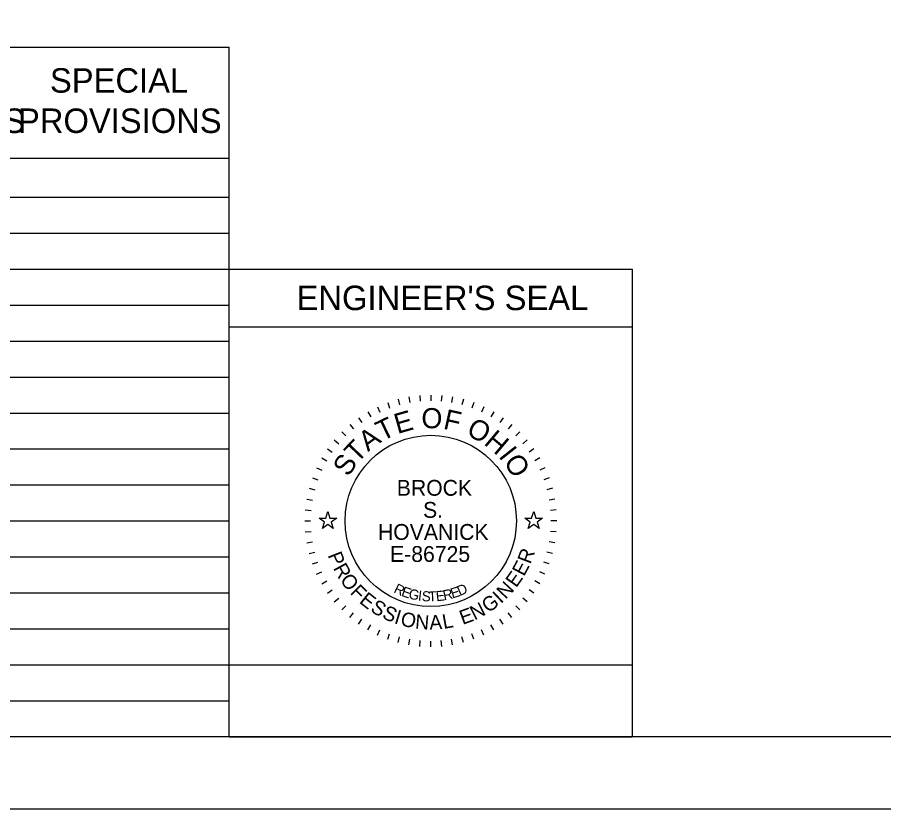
# Model space of a CAD drawing. Extents: x 0 to 34, y 0 to 22.
# Drawn here: x 22.13 to 28.15, y 0 to 5.5 of the extents above; entities that cross this region are included whole.
import ezdxf

# ---------------------------------------------------------------- set-up
doc = ezdxf.new("R2010")
doc.units = 0
for name, color, linetype in [('Default', 7, 'Continuous'), ('SH_Border', 7, 'Continuous'), ('SH_Cut_Line', 7, 'Continuous'), ('SH_Data', 7, 'Continuous'), ('SH_Text', 7, 'Continuous')]:
    doc.layers.add(name, color=color, linetype=linetype)

msp = doc.modelspace()

# ---------------------------------------------------------------- linework, layer by layer
at = {"layer": 'Default'}
for points in [[(24.2236, 2.02), (24.2705, 2.02), (24.285, 2.0645), (24.2995, 2.02), (24.3464, 2.02), (24.3085, 1.9924), (24.323, 1.9478), (24.285, 1.9754), (24.247, 1.9478), (24.2615, 1.9924)], [(25.6536, 2.02), (25.7005, 2.02), (25.715, 2.0645), (25.7295, 2.02), (25.7764, 2.02), (25.7385, 1.9924), (25.753, 1.9478), (25.715, 1.9754), (25.677, 1.9478), (25.6915, 1.9924)]]:
    msp.add_lwpolyline(points, close=True, dxfattribs=at)
at = {"layer": 'SH_Border'}
msp.add_lwpolyline([(1.5, 21.5), (33.5, 21.5), (33.5, 0.5), (1.5, 0.5)], close=True, dxfattribs=at)
at = {"layer": 'SH_Cut_Line'}
msp.add_lwpolyline([(0, 0), (34, 0), (34, 22), (0, 22)], close=True, dxfattribs=at)
at = {"layer": 'SH_Data'}
for p, q in [((10.15, 5.2917), (23.6, 5.2917)), ((23.6, 0.5), (23.6, 5.2917)), ((10.15, 4.5209), (23.6, 4.5209)), ((10.15, 4.25), (23.6, 4.25)), ((10.15, 4), (23.6, 4)), ((10.15, 3.75), (23.6, 3.75)), ((23.6, 0.5), (23.6, 3.75)), ((23.6, 3.75), (26.4, 3.75)), ((26.4, 3.75), (26.4, 0.5)), ((10.15, 3.5), (23.6, 3.5)), ((23.6, 3.35), (26.4, 3.35)), ((10.15, 3.25), (23.6, 3.25)), ((10.15, 3), (23.6, 3)), ((24.7735, 2.8452), (24.7839, 2.8065)), ((24.8481, 2.8617), (24.855, 2.8223)), ((24.9237, 2.8717), (24.9272, 2.8318)), ((25, 2.875), (25, 2.835)), ((25.0763, 2.8717), (25.0728, 2.8318)), ((25.1519, 2.8617), (25.145, 2.8223)), ((25.2265, 2.8452), (25.2161, 2.8065)), ((24.6302, 2.793), (24.6471, 2.7568)), ((24.7007, 2.8222), (24.7144, 2.7846)), ((25.2993, 2.8222), (25.2856, 2.7846)), ((25.3698, 2.793), (25.3529, 2.7568)), ((10.15, 2.75), (23.6, 2.75)), ((24.4981, 2.7168), (24.5211, 2.684)), ((24.5625, 2.7578), (24.5825, 2.7231)), ((25.4375, 2.7578), (25.4175, 2.7231)), ((25.5019, 2.7168), (25.4789, 2.684)), ((24.4376, 2.6703), (24.4633, 2.6396)), ((25.5624, 2.6703), (25.5367, 2.6396)), ((24.3813, 2.6187), (24.4096, 2.5904)), ((25.6187, 2.6187), (25.5904, 2.5904)), ((24.3297, 2.5624), (24.3604, 2.5367)), ((25.6703, 2.5624), (25.6396, 2.5367)), ((10.15, 2.5), (23.6, 2.5)), ((24.2832, 2.5019), (24.316, 2.4789)), ((25.7168, 2.5019), (25.684, 2.4789)), ((24.2422, 2.4375), (24.2769, 2.4175)), ((25.7578, 2.4375), (25.7231, 2.4175)), ((24.207, 2.3698), (24.2432, 2.3529)), ((25.793, 2.3698), (25.7568, 2.3529)), ((24.1778, 2.2993), (24.2154, 2.2856)), ((25.8222, 2.2993), (25.7846, 2.2856)), ((10.15, 2.25), (23.6, 2.25)), ((24.1548, 2.2265), (24.1935, 2.2161)), ((25.8452, 2.2265), (25.8065, 2.2161)), ((24.1383, 2.1519), (24.1777, 2.145)), ((25.8617, 2.1519), (25.8223, 2.145)), ((24.1283, 2.0763), (24.1682, 2.0728)), ((25.8717, 2.0763), (25.8318, 2.0728)), ((10.15, 2), (23.6, 2)), ((24.125, 2), (24.165, 2)), ((25.875, 2), (25.835, 2)), ((24.1283, 1.9237), (24.1682, 1.9272)), ((25.8717, 1.9237), (25.8318, 1.9272)), ((24.1383, 1.8481), (24.1777, 1.855)), ((25.8617, 1.8481), (25.8223, 1.855)), ((10.15, 1.75), (23.6, 1.75)), ((24.1548, 1.7735), (24.1935, 1.7839)), ((25.8452, 1.7735), (25.8065, 1.7839)), ((24.1778, 1.7007), (24.2154, 1.7144)), ((25.8222, 1.7007), (25.7846, 1.7144)), ((24.207, 1.6302), (24.2432, 1.6471)), ((25.793, 1.6302), (25.7568, 1.6471)), ((24.2422, 1.5625), (24.2769, 1.5825)), ((25.7578, 1.5625), (25.7231, 1.5825)), ((24.2832, 1.4981), (24.316, 1.5211)), ((25.7168, 1.4981), (25.684, 1.5211)), ((10.15, 1.5), (23.6, 1.5)), ((24.3297, 1.4376), (24.3604, 1.4633)), ((25.6703, 1.4376), (25.6396, 1.4633)), ((24.3813, 1.3813), (24.4096, 1.4096)), ((25.6187, 1.3813), (25.5904, 1.4096)), ((24.4376, 1.3297), (24.4633, 1.3604)), ((25.5624, 1.3297), (25.5367, 1.3604)), ((24.4981, 1.2832), (24.5211, 1.316)), ((24.5625, 1.2422), (24.5825, 1.2769)), ((25.4375, 1.2422), (25.4175, 1.2769)), ((25.5019, 1.2832), (25.4789, 1.316)), ((10.15, 1.25), (23.6, 1.25)), ((24.6302, 1.207), (24.6471, 1.2432)), ((24.7007, 1.1778), (24.7144, 1.2154)), ((25.2993, 1.1778), (25.2856, 1.2154)), ((25.3698, 1.207), (25.3529, 1.2432)), ((24.7735, 1.1548), (24.7839, 1.1935)), ((24.8481, 1.1383), (24.855, 1.1777)), ((24.9237, 1.1283), (24.9272, 1.1682)), ((25, 1.125), (25, 1.165)), ((25.0763, 1.1283), (25.0728, 1.1682)), ((25.1519, 1.1383), (25.145, 1.1777)), ((25.2265, 1.1548), (25.2161, 1.1935)), ((10.15, 1), (23.6, 1)), ((10.15, 0.75), (23.6, 0.75)), ((23.6, 0.5), (26.4, 0.5))]:
    msp.add_line(p, q, dxfattribs=at)
msp.add_lwpolyline([(23.6, 0.5), (23.6, 1), (26.4, 1), (26.4, 0.5)], close=True, dxfattribs=at)
msp.add_circle((25, 2), 0.595, dxfattribs=at)

# ---------------------------------------------------------------- texts
for s, height, p in [("ENGINEER'S SEAL", 0.17, (24.0676, 3.465)), ('BROCK', 0.11, (24.7639, 2.1749)), ('S.', 0.11, (24.9465, 2.0216)), ('HOVANICK', 0.11, (24.6332, 1.8684)), ('E-86725', 0.11, (24.7173, 1.7151))]:
    msp.add_text(s, height=height, dxfattribs=at).set_placement(p)
for s, height, rotation, p in [('E', 0.14, 15.75706, (24.7684, 2.6038)), ('O', 0.14, 359.78119, (24.9347, 2.6443)), ('F', 0.14, 347.43619, (25.0811, 2.6417)), ('T', 0.14, 25.71674, (24.6616, 2.5518)), ('O', 0.14, 332.25863, (25.2398, 2.6015)), ('A', 0.14, 36.47472, (24.5634, 2.4781)), ('H', 0.14, 319.91363, (25.3632, 2.5361)), ('T', 0.14, 46.4344, (24.4883, 2.3964)), ('I', 0.14, 308.36695, (25.4665, 2.4483)), ('S', 0.14, 57.19238, (24.4281, 2.3014)), ('O', 0.14, 303.14906, (25.5021, 2.4089)), ('R', 0.1, 69.23216, (25.6919, 1.6954)), ('P', 0.1, 291.49398, (24.2823, 1.7621)), ('R', 0.1, 298.73106, (24.319, 1.6717)), ('E', 0.1, 61.99508, (25.6476, 1.6098)), ('O', 0.1, 306.46664, (24.3655, 1.5883)), ('E', 0.1, 54.75801, (25.5933, 1.5314)), ('N', 0.1, 47.02243, (25.5202, 1.4508)), ('F', 0.1, 314.7068, (24.4343, 1.4983)), ('E', 0.1, 321.43929, (24.4978, 1.4348)), ('R', 0.07, 334.48695, (24.7375, 1.5051)), ('E', 0.07, 341.03996, (24.7906, 1.4801)), ('G', 0.07, 347.47515, (24.8414, 1.4618)), ('I', 0.07, 353.78581, (24.9091, 1.4468)), ('S', 0.07, 356.89262, (24.9358, 1.4429)), ('T', 0.07, 3.00609, (24.9857, 1.4387)), ('E', 0.07, 6.01169, (25.0389, 1.4412)), ('R', 0.07, 11.91844, (25.0925, 1.4474)), ('E', 0.07, 17.68363, (25.1498, 1.4602)), ('D', 0.07, 23.30524, (25.201, 1.477)), ('I', 0.1, 43.28703, (25.4868, 1.4214)), ('S', 0.1, 328.67637, (24.5743, 1.3752)), ('G', 0.1, 35.04687, (25.3981, 1.357)), ('S', 0.1, 335.91345, (24.6564, 1.3266)), ('E', 0.1, 20.07421, (25.2212, 1.277)), ('N', 0.1, 27.31129, (25.3045, 1.3075)), ('I', 0.1, 343.15053, (24.7406, 1.2897)), ('O', 0.1, 346.88592, (24.7839, 1.2751)), ('N', 0.1, 355.12608, (24.8888, 1.2517)), ('A', 0.1, 2.86166, (24.9923, 1.2437)), ('L', 0.1, 10.09874, (25.0894, 1.249))]:
    msp.add_text(s, height=height, rotation=rotation, dxfattribs=at).set_placement(p)
at = {"layer": 'SH_Text'}
for s, p in [('SPECIAL', (22.3542, 4.9763)), ('SPECIFICATIONS', (20.2871, 4.6963)), ('PROVISIONS', (22.1323, 4.6963))]:
    msp.add_text(s, height=0.17, dxfattribs=at).set_placement(p)

doc.saveas('drawing.dxf')
